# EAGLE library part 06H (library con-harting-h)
CONNECTOR
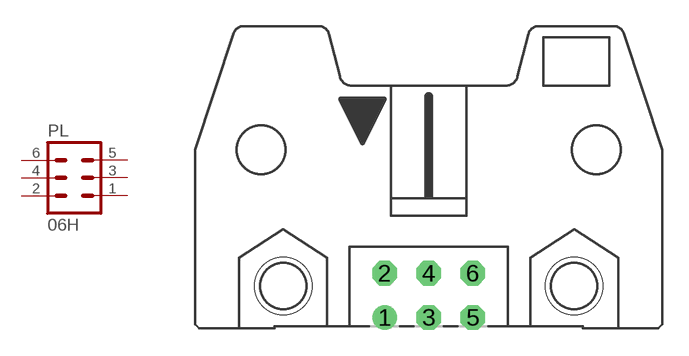
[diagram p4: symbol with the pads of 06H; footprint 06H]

Designator prefix PL

## 06H (OC_FARNELL: unknown; OC_NEWARK: unknown)  [06H]
1  1  pas
2  2  pas
3  3  pas
4  4  pas
5  5  pas
6  6  pas

## Footprint 06H (pad centres in mm)
CONNECTOR
drill 0.914 round: 1 -2.54,-1.27
drill 0.914 octagon: 2 -2.54,1.27; 3 0,-1.27; 4 0,1.27; 5 2.54,-1.27; 6 2.54,1.27
hole 3.302 at -8.382,0.533
hole 3.302 at 8.382,0.533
